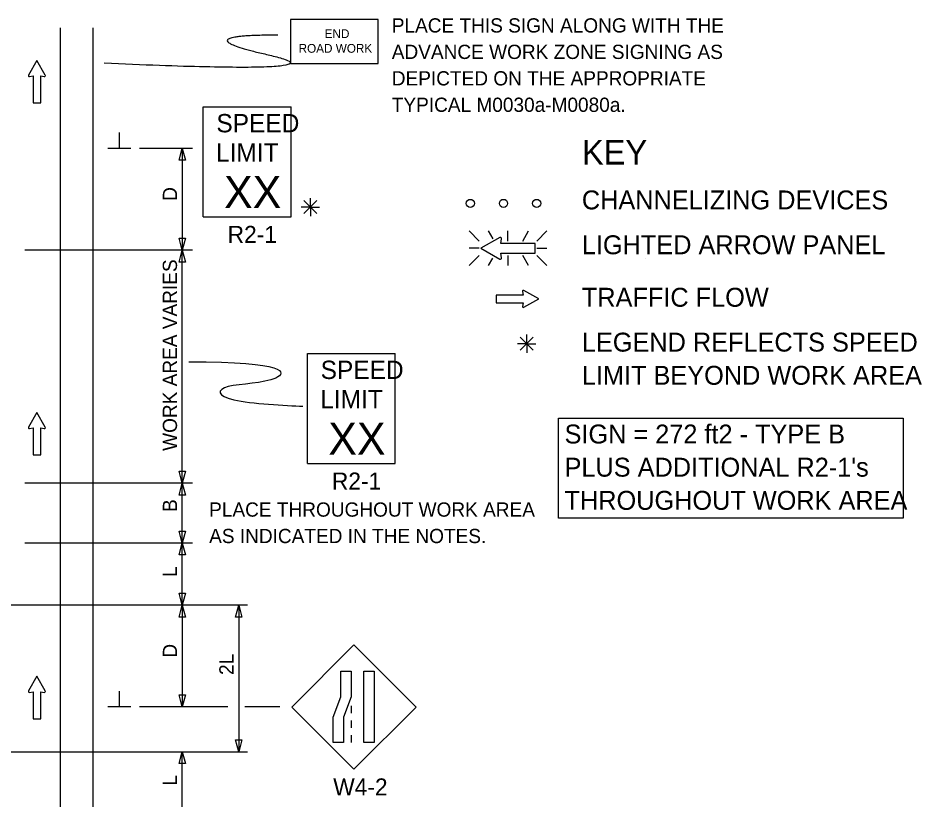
# Model space of a CAD drawing. Extents: x 16735 to 18480, y 5523 to 6928.
# Drawn here: x 16983.9 to 17428.3, y 6539.6 to 6923.9 of the extents above; entities that cross this region are included whole.
import ezdxf

# ---------------------------------------------------------------- set-up
doc = ezdxf.new("R2010")
doc.units = 0
for name, color, linetype in [('MT_SCRATCH_LEVEL_E', 7, 'Continuous'), ('PAVT_EDGE_EX', 7, 'Continuous'), ('TRAFFIC_SIGNS_PR', 7, 'Continuous'), ('TYPICAL_TEXT_DIMEN_EX', 7, 'Continuous'), ('TYPICAL_TEXT_DIMEN_PR', 7, 'Continuous')]:
    doc.layers.add(name, color=color, linetype=linetype)

msp = doc.modelspace()

# ---------------------------------------------------------------- linework, layer by layer
at = {"layer": 'MT_SCRATCH_LEVEL_E'}
for p, q in [((16993.16, 6903.1), (16989.05, 6895.86)), ((16997.31, 6895.86), (16993.16, 6903.1)), ((16989.53, 6895.17), (16991.31, 6895.49)), ((16991.31, 6895.49), (16991.31, 6882.23)), ((16995.05, 6882.23), (16995.05, 6895.49)), ((16995.05, 6895.49), (16996.83, 6895.17)), ((16991.31, 6882.23), (16995.05, 6882.23)), ((17232.31, 6787.73), (17219.05, 6787.73)), ((17219.05, 6787.73), (17219.05, 6783.99)), ((17232, 6789.51), (17232.31, 6787.73)), ((17239.92, 6785.88), (17232.68, 6789.99)), ((17219.05, 6783.99), (17232.31, 6783.99)), ((17232.31, 6783.99), (17232, 6782.21)), ((17232.68, 6781.74), (17239.92, 6785.88)), ((16993.16, 6730.05), (16989.05, 6722.81)), ((16997.31, 6722.81), (16993.16, 6730.05)), ((16989.53, 6722.12), (16991.31, 6722.44)), ((16991.31, 6722.44), (16991.31, 6709.18)), ((16995.05, 6709.18), (16995.05, 6722.44)), ((16995.05, 6722.44), (16996.83, 6722.12)), ((16991.31, 6709.18), (16995.05, 6709.18)), ((16993.16, 6600.4), (16989.05, 6593.16)), ((16997.31, 6593.16), (16993.16, 6600.4)), ((16989.53, 6592.48), (16991.31, 6592.79)), ((16991.31, 6592.79), (16991.31, 6579.54)), ((16995.05, 6579.54), (16995.05, 6592.79)), ((16995.05, 6592.79), (16996.83, 6592.48)), ((16991.31, 6579.54), (16995.05, 6579.54))]:
    msp.add_line(p, q, dxfattribs=at)
for centre, start, end in [((16989.46, 6895.63), 150.4248, 279.9638), ((16996.9, 6895.63), 260.0362, 29.7731), ((17232.45, 6789.59), 60.4248, 189.9638), ((17232.45, 6782.15), 170.0362, 299.7731), ((16989.46, 6722.58), 150.4248, 279.9638), ((16996.9, 6722.58), 260.0362, 29.7731), ((16989.46, 6592.94), 150.4248, 279.9638), ((16996.9, 6592.94), 260.0362, 29.7731)]:
    msp.add_arc(centre, 0.463, start, end, dxfattribs=at)
at = {"layer": 'PAVT_EDGE_EX'}
for p, q in [((17004.63, 6919.19), (17004.63, 6059.77)), ((17020.63, 6919.19), (17020.63, 6059.77))]:
    msp.add_line(p, q, dxfattribs=at)
at = {"layer": 'TRAFFIC_SIGNS_PR'}
for p, q in [((17074.95, 6880.28), (17118.15, 6880.28)), ((17074.95, 6826.28), (17074.95, 6880.28)), ((17118.15, 6826.28), (17118.15, 6880.28)), ((17074.95, 6826.28), (17118.15, 6826.28)), ((17205.73, 6819.26), (17210.66, 6814.33)), ((17217.49, 6815.44), (17215.29, 6819.27)), ((17224.81, 6814.33), (17224.81, 6819.27)), ((17232.05, 6814.33), (17234.9, 6819.27)), ((17238.96, 6814.33), (17243.9, 6819.27)), ((17210.66, 6810.78), (17205.73, 6810.78)), ((17238.96, 6810.78), (17243.9, 6810.78)), ((17205.73, 6802.29), (17210.66, 6807.22)), ((17215.24, 6802.29), (17217.36, 6805.95)), ((17224.81, 6807.22), (17224.81, 6802.29)), ((17234.94, 6802.29), (17232.09, 6807.22)), ((17238.96, 6807.22), (17243.9, 6802.28)), ((17126.21, 6759.04), (17169.41, 6759.04)), ((17126.21, 6705.04), (17126.21, 6759.04)), ((17169.41, 6705.04), (17169.41, 6759.04)), ((17126.21, 6705.04), (17169.41, 6705.04)), ((17149.06, 6615.78), (17118.51, 6585.24)), ((17179.6, 6585.24), (17149.06, 6615.78)), ((17118.51, 6585.24), (17149.06, 6554.69)), ((17147.65, 6585.79), (17147.65, 6582.19)), ((17149.06, 6554.69), (17179.6, 6585.24)), ((17147.65, 6578.59), (17147.65, 6574.99)), ((17147.65, 6571.39), (17147.65, 6567.79))]:
    msp.add_line(p, q, dxfattribs=at)
for points in [[(17117.81, 6901.54), (17161.01, 6901.54), (17161.01, 6923.14), (17117.81, 6923.14)], [(17147.65, 6602.94), (17147.65, 6590.36), (17143.89, 6580.37), (17143.89, 6567.79), (17138.84, 6567.79), (17138.84, 6580.37), (17142.6, 6590.36), (17142.6, 6602.94)], [(17159.06, 6602.94), (17159.06, 6567.79), (17154, 6567.79), (17154, 6602.94)]]:
    msp.add_lwpolyline(points, close=True, dxfattribs=at)
for points in [[(17220.74, 6816.05), (17211.45, 6810.78), (17220.74, 6805.46)], [(17221.62, 6806.08), (17221.22, 6808.35), (17238.23, 6808.35), (17238.23, 6813.15), (17221.22, 6813.15), (17221.62, 6815.43)]]:
    msp.add_lwpolyline(points, dxfattribs=at)
for centre in [(17206.29, 6832.81), (17222.59, 6832.81), (17238.89, 6832.81)]:
    msp.add_circle(centre, 2, dxfattribs=at)
for centre, radius, start, end in [((17221.03, 6815.53), 0.598, 350.7308, 118.8916), ((17221.03, 6805.98), 0.597, 241.4833, 9.9593)]:
    msp.add_arc(centre, radius, start, end, dxfattribs=at)
msp.add_open_spline([(17111.64, 6915.52), (17064.41, 6915.52), (17149.43, 6896.18), (17026.33, 6901.67)], degree=2, dxfattribs=at)
at = {"layer": 'TYPICAL_TEXT_DIMEN_EX'}
msp.add_lwpolyline([(17249.6, 6727.22), (17419.06, 6727.22), (17419.06, 6678.03), (17249.6, 6678.03)], close=True, dxfattribs=at)
at = {"layer": 'TYPICAL_TEXT_DIMEN_PR'}
for p, q in [((17033.76, 6859.85), (17033.76, 6867.64)), ((17039.38, 6859.85), (17028.13, 6859.85)), ((17069.63, 6859.85), (17043.63, 6859.85)), ((17063.06, 6853.99), (17064.63, 6859.85)), ((17064.63, 6859.85), (17064.63, 6809.85)), ((17064.63, 6859.85), (17066.2, 6853.99)), ((17064.63, 6853.99), (17063.06, 6853.99)), ((17066.2, 6853.99), (17064.63, 6853.99)), ((17127.69, 6830.99), (17127.69, 6835.44)), ((17127.69, 6830.99), (17123.16, 6830.99)), ((17130.88, 6834.18), (17124.5, 6827.8)), ((17124.51, 6834.18), (17130.88, 6827.8)), ((17127.69, 6830.99), (17130.88, 6830.99)), ((17127.69, 6830.99), (17132.17, 6830.99)), ((17127.69, 6830.99), (17127.69, 6826.49)), ((17064.63, 6809.85), (17063.06, 6815.71)), ((17063.06, 6815.71), (17064.63, 6815.71)), ((17064.63, 6815.71), (17066.2, 6815.71)), ((17066.2, 6815.71), (17064.63, 6809.85)), ((17069.63, 6809.85), (16987.24, 6809.85)), ((17063.06, 6803.99), (17064.63, 6809.85)), ((17064.63, 6695.32), (17064.63, 6809.85)), ((17064.63, 6809.85), (17066.2, 6803.99)), ((17064.63, 6803.99), (17063.06, 6803.99)), ((17066.2, 6803.99), (17064.63, 6803.99)), ((17234.07, 6763.87), (17234.07, 6768.32)), ((17234.07, 6763.87), (17229.54, 6763.87)), ((17230.88, 6767.05), (17237.26, 6760.68)), ((17237.26, 6767.05), (17230.88, 6760.68)), ((17234.07, 6763.87), (17237.26, 6763.87)), ((17234.07, 6763.87), (17238.55, 6763.87)), ((17234.07, 6763.87), (17234.07, 6759.37)), ((17064.63, 6695.32), (17063.06, 6701.18)), ((17063.06, 6701.18), (17064.63, 6701.18)), ((17064.63, 6701.18), (17066.2, 6701.18)), ((17066.2, 6701.18), (17064.63, 6695.32)), ((17069.63, 6695.32), (16987.24, 6695.32)), ((17063.06, 6689.45), (17064.63, 6695.32)), ((17064.63, 6665.89), (17064.63, 6695.32)), ((17064.63, 6695.32), (17066.2, 6689.45)), ((17064.63, 6689.45), (17063.06, 6689.45)), ((17066.2, 6689.45), (17064.63, 6689.45)), ((17064.63, 6665.89), (17063.06, 6671.75)), ((17063.06, 6671.75), (17064.63, 6671.75)), ((17064.63, 6671.75), (17066.2, 6671.75)), ((17066.2, 6671.75), (17064.63, 6665.89)), ((17069.63, 6665.89), (16987.24, 6665.89)), ((17063.06, 6660.03), (17064.63, 6665.89)), ((17064.63, 6635.32), (17064.63, 6665.89)), ((17064.63, 6665.89), (17066.2, 6660.03)), ((17064.63, 6660.03), (17063.06, 6660.03)), ((17066.2, 6660.03), (17064.63, 6660.03)), ((17064.63, 6635.32), (17063.06, 6641.19)), ((17063.06, 6641.19), (17064.63, 6641.19)), ((17064.63, 6641.19), (17066.2, 6641.19)), ((17066.2, 6641.19), (17064.63, 6635.32)), ((17096.68, 6635.32), (16965.53, 6635.32)), ((17063.06, 6629.46), (17064.63, 6635.32)), ((17064.63, 6635.32), (17064.63, 6585.32)), ((17064.63, 6635.32), (17066.2, 6629.46)), ((17090.87, 6629.46), (17092.44, 6635.32)), ((17092.44, 6635.32), (17094.01, 6629.46)), ((17092.44, 6635.32), (17092.44, 6563.32)), ((17064.63, 6629.46), (17063.06, 6629.46)), ((17066.2, 6629.46), (17064.63, 6629.46)), ((17092.44, 6629.46), (17090.87, 6629.46)), ((17094.01, 6629.46), (17092.44, 6629.46)), ((17033.76, 6585.32), (17033.76, 6593.11)), ((17064.63, 6585.32), (17063.06, 6591.19)), ((17063.06, 6591.19), (17064.63, 6591.19)), ((17064.63, 6591.19), (17066.2, 6591.19)), ((17066.2, 6591.19), (17064.63, 6585.32)), ((17092.44, 6590.19), (17092.44, 6586.43)), ((17039.38, 6585.32), (17028.13, 6585.32)), ((17087.09, 6585.32), (17043.63, 6585.32)), ((17112.63, 6585.32), (17095.46, 6585.32)), ((17092.44, 6563.32), (17090.87, 6569.19)), ((17090.87, 6569.19), (17092.44, 6569.19)), ((17092.44, 6569.19), (17094.01, 6569.19)), ((17094.01, 6569.19), (17092.44, 6563.32)), ((16965.53, 6563.32), (17096.68, 6563.32)), ((17063.06, 6557.46), (17064.63, 6563.32)), ((17064.63, 6532.76), (17064.63, 6563.32)), ((17064.63, 6563.32), (17066.2, 6557.46)), ((17064.63, 6557.46), (17063.06, 6557.46)), ((17066.2, 6557.46), (17064.63, 6557.46))]:
    msp.add_line(p, q, dxfattribs=at)
for points, degree in [([(17292.54, 6805.67), (17292.55, 6805.67), (17292.56, 6805.67), (17292.56, 6805.67)], 2), ([(17067.94, 6755.02), (17116.41, 6755.02), (17116.41, 6744.27), (17081.49, 6744.27), (17081.49, 6735.22), (17115.7, 6733.45), (17123.99, 6733.17)], 3)]:
    msp.add_open_spline(points, degree=degree, dxfattribs=at)

# ---------------------------------------------------------------- texts
at = {"layer": 'TRAFFIC_SIGNS_PR'}
for s, height, p in [('PLACE THIS SIGN ALONG WITH THE', 7, (17167.68, 6916.8)), ('END', 4.31, (17134.69, 6914.06)), ('ROAD WORK', 4.31, (17121.87, 6906.87)), ('ADVANCE WORK ZONE SIGNING AS', 7, (17167.68, 6903.8)), ('DEPICTED ON THE APPROPRIATE', 7, (17167.68, 6890.8)), ('TYPICAL M0030a-M0080a.', 7, (17167.68, 6877.8)), ('SPEED', 9, (17081.44, 6867.74)), ('LIMIT', 9, (17081.26, 6853.34)), ('XX', 15.785, (17085.2, 6830.5)), ('R2-1', 8.37, (17086.96, 6813.4)), ('SPEED', 9, (17132.7, 6746.51)), ('LIMIT', 9, (17132.52, 6732.11)), ('XX', 15.785, (17136.46, 6709.27)), ('R2-1', 8.37, (17138.22, 6692.17)), ('PLACE THROUGHOUT WORK AREA', 7, (17077.88, 6678.84)), ('AS INDICATED IN THE NOTES.', 7, (17077.88, 6665.84)), ('W4-2', 8.37, (17138.88, 6541.82))]:
    msp.add_text(s, height=height, dxfattribs=at).set_placement(p)
at = {"layer": 'TYPICAL_TEXT_DIMEN_EX'}
for s, height, p in [('KEY', 12, (17261.13, 6851.92)), ('CHANNELIZING DEVICES', 9.3, (17261.13, 6829.87)), ('LIGHTED ARROW PANEL', 9.3, (17261.13, 6807.82)), ('TRAFFIC FLOW', 9.3, (17261.13, 6782.02)), ('LEGEND REFLECTS SPEED', 9.3, (17261.13, 6759.97)), ('LIMIT BEYOND WORK AREA', 9.3, (17261.13, 6743.67)), ('SIGN = 272 ft2 - TYPE B', 9.3, (17252.62, 6714.81)), ("PLUS ADDITIONAL R2-1's", 9.3, (17252.62, 6698.51)), ('THROUGHOUT WORK AREA', 9.3, (17252.62, 6682.21))]:
    msp.add_text(s, height=height, dxfattribs=at).set_placement(p)
at = {"layer": 'TYPICAL_TEXT_DIMEN_PR'}
for s, p in [('D', (17062.08, 6834.07)), ('WORK AREA VARIES', (17062.08, 6711.17)), ('B', (17062.08, 6681.15)), ('L', (17062.08, 6649.18)), ('D', (17062.08, 6609.54)), ('2L', (17089.88, 6601.05)), ('L', (17062.08, 6546.62))]:
    msp.add_text(s, height=7, rotation=90, dxfattribs=at).set_placement(p)

doc.saveas('drawing.dxf')
